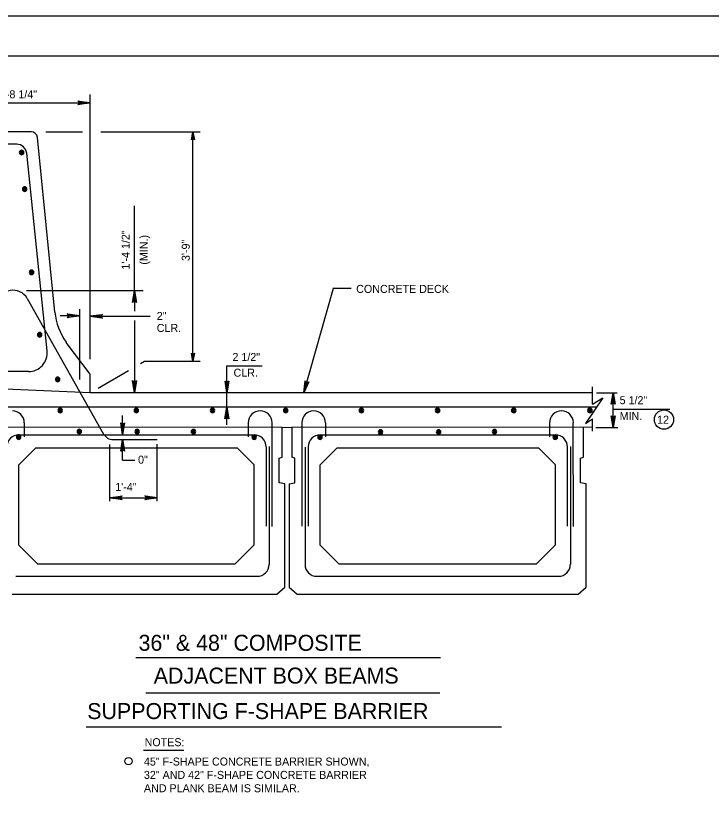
# Model space of a CAD drawing. Extents: x 639331 to 643089, y 299088 to 300975.
# Drawn here: x 641559.1 to 641819.9, y 300574.6 to 300869.7 of the extents above; entities that cross this region are included whole.
import ezdxf

# ---------------------------------------------------------------- set-up
doc = ezdxf.new("R2010")
doc.units = 0
doc.layers.add('1', color=7, linetype='Continuous')
doc.layers.add('PLT-BNDY', color=7, linetype='Continuous')

msp = doc.modelspace()

# ---------------------------------------------------------------- linework, layer by layer
at = {"layer": '1'}
for p, q in [((641433.06, 300854.66), (642219.06, 300854.66)), ((641587.01, 300831.44), (641587.01, 300840.17)), ((641587.01, 300740.96), (641587.01, 300840.17)), ((641540, 300837.03), (641587.01, 300837.03)), ((641564.79, 300826.1), (641541.71, 300826.1)), ((641570.43, 300826.1), (641584.15, 300826.1)), ((641590.95, 300826.1), (641628.21, 300826.1)), ((641625.51, 300740.22), (641625.51, 300826.1)), ((641573.76, 300758.55), (641567.19, 300824.01)), ((641559.45, 300821.54), (641548.32, 300821.54)), ((641561.41, 300818.62), (641561.41, 300818.62)), ((641560.77, 300818.55), (641560.77, 300818.55)), ((641570.86, 300744.07), (641563.19, 300818.15)), ((641561.92, 300804.86), (641561.92, 300804.86)), ((641562.55, 300804.92), (641562.55, 300804.92)), ((641603.65, 300766.76), (641603.65, 300798.41)), ((641564.5, 300773.67), (641564.5, 300773.67)), ((641565.13, 300773.73), (641565.13, 300773.73)), ((641563.09, 300766.76), (641606.91, 300766.76)), ((641603.65, 300766.76), (641603.65, 300758.98)), ((641667.09, 300728.42), (641678.26, 300767.52)), ((641678.01, 300767.52), (641684.88, 300767.52)), ((641563.35, 300763.75), (641592.04, 300712.92)), ((641583.02, 300759.67), (641583.02, 300733.41)), ((641583, 300757.24), (641575.79, 300757.24)), ((641586.99, 300757.03), (641609.51, 300757.03)), ((641603.65, 300755.42), (641603.65, 300728.42)), ((641567.52, 300750.29), (641567.52, 300750.29)), ((641568.15, 300750.35), (641568.15, 300750.35)), ((641587.01, 300735.34), (641578.04, 300747.23)), ((641605.86, 300739.33), (641607.38, 300740.22)), ((641607.38, 300740.22), (641628.21, 300740.22)), ((641563.86, 300736.31), (641554.35, 300736.33)), ((641590, 300730.15), (641601.38, 300736.74)), ((641638.26, 300722.94), (641638.26, 300738.51)), ((641638.26, 300738.51), (641651.49, 300738.51)), ((641574.28, 300733.54), (641574.28, 300733.54)), ((641574.91, 300733.6), (641574.91, 300733.6)), ((641587.01, 300728.42), (641587.01, 300735.34)), ((641587.01, 300728.42), (641542, 300730.28)), ((641775.31, 300724.07), (641775.31, 300730.57)), ((641775.31, 300728.42), (641587.01, 300728.42)), ((641638.26, 300722.94), (641638.26, 300728.42)), ((641776.84, 300728.42), (641784.57, 300728.42)), ((641783.1, 300715.42), (641783.1, 300728.42)), ((641779.23, 300726.46), (641772.75, 300716.91)), ((641775.31, 300724.07), (641779.23, 300726.46)), ((641776.77, 300722.94), (641545.67, 300722.94)), ((641575.22, 300721.92), (641575.22, 300721.92)), ((641575.85, 300721.98), (641575.85, 300721.98)), ((641775.31, 300722.94), (641587.01, 300722.94)), ((641603.78, 300721.92), (641603.78, 300721.92)), ((641604.41, 300721.98), (641604.41, 300721.98)), ((641632.77, 300721.98), (641632.77, 300721.98)), ((641633.4, 300721.92), (641633.4, 300721.92)), ((641638.26, 300716.35), (641638.26, 300722.94)), ((641659.77, 300721.92), (641659.77, 300721.92)), ((641660.4, 300721.98), (641660.4, 300721.98)), ((641688.19, 300721.92), (641688.19, 300721.92)), ((641688.83, 300721.98), (641688.83, 300721.98)), ((641716.75, 300721.92), (641716.75, 300721.92)), ((641717.39, 300721.98), (641717.39, 300721.98)), ((641745.74, 300721.98), (641745.74, 300721.98)), ((641746.37, 300721.92), (641746.37, 300721.92)), ((641774.3, 300721.98), (641774.3, 300721.98)), ((641774.93, 300721.92), (641774.93, 300721.92)), ((641783.1, 300722.29), (641804.35, 300722.29)), ((641599.18, 300712.62), (641599.18, 300719.83)), ((641772.75, 300716.91), (641775.31, 300718.62)), ((641775.31, 300713.94), (641775.31, 300718.62)), ((641659, 300715.42), (641548.62, 300715.54)), ((641562.28, 300717.14), (641562.28, 300711.82)), ((641646.29, 300717.16), (641646.29, 300711.85)), ((641655.25, 300678.3), (641655.2, 300717.16)), ((641659, 300715.42), (641662.59, 300715.54)), ((641659, 300704.3), (641659, 300715.42)), ((641775.31, 300715.42), (641662.59, 300715.54)), ((641662.59, 300715.54), (641662.59, 300704.3)), ((641666.34, 300717.14), (641666.34, 300678.42)), ((641675.25, 300717.14), (641675.25, 300711.82)), ((641759.26, 300717.16), (641759.26, 300711.85)), ((641768.22, 300678.3), (641768.17, 300717.16)), ((641771.97, 300704.3), (641771.97, 300715.42)), ((641776.6, 300715.42), (641784.8, 300715.42)), ((641560.25, 300712.62), (641648.5, 300712.62)), ((641582.41, 300714.01), (641582.41, 300714.01)), ((641604.09, 300714), (641604.09, 300714)), ((641604.73, 300714.06), (641604.73, 300714.06)), ((641625.18, 300713.96), (641625.18, 300713.96)), ((641673.22, 300712.62), (641761.47, 300712.62)), ((641695.34, 300713.8), (641695.34, 300713.8)), ((641717.13, 300713.85), (641717.13, 300713.85)), ((641717.76, 300713.91), (641717.76, 300713.91)), ((641738.1, 300713.96), (641738.1, 300713.96)), ((641559.66, 300711.92), (641559.66, 300711.92)), ((641560.29, 300711.99), (641560.29, 300711.99)), ((641595.58, 300710.83), (641612.08, 300710.83)), ((641599.18, 300703.16), (641599.18, 300710.83)), ((641647.95, 300711.91), (641647.95, 300711.91)), ((641648.59, 300711.97), (641648.59, 300711.97)), ((641673.34, 300712.08), (641673.34, 300712.08)), ((641760.85, 300711.91), (641760.85, 300711.91)), ((641761.83, 300711.73), (641761.83, 300711.73)), ((641560.25, 300701.42), (641566.62, 300707.8)), ((641566.62, 300707.8), (641642.12, 300707.8)), ((641594.38, 300687.75), (641594.38, 300709.02)), ((641612.07, 300687.75), (641612.07, 300709.16)), ((641642.12, 300707.8), (641648.5, 300701.42)), ((641652.95, 300708.16), (641652.95, 300678.42)), ((641654.12, 300708.3), (641654.12, 300664.05)), ((641667.59, 300708.05), (641667.59, 300664.05)), ((641668.76, 300708.16), (641668.76, 300678.42)), ((641673.22, 300701.42), (641679.6, 300707.8)), ((641679.6, 300707.8), (641755.09, 300707.8)), ((641755.09, 300707.8), (641761.47, 300701.42)), ((641765.92, 300708.16), (641765.92, 300678.42)), ((641767.09, 300708.3), (641767.09, 300664.05)), ((641657.87, 300703.92), (641659, 300704.3)), ((641657.87, 300694.67), (641657.87, 300703.92)), ((641663.72, 300703.92), (641662.59, 300704.3)), ((641663.72, 300694.67), (641663.72, 300703.92)), ((641770.84, 300703.92), (641771.97, 300704.3)), ((641770.84, 300694.67), (641770.84, 300703.92)), ((641560.25, 300671.3), (641560.25, 300701.42)), ((641599.18, 300703.16), (641603.76, 300703.16)), ((641648.5, 300671.42), (641648.5, 300701.42)), ((641673.22, 300671.3), (641673.22, 300701.42)), ((641761.47, 300671.42), (641761.47, 300701.42)), ((641660, 300694.3), (641657.87, 300694.67)), ((641661.59, 300694.3), (641663.72, 300694.67)), ((641772.97, 300694.3), (641770.84, 300694.67)), ((641660, 300655.55), (641660, 300694.3)), ((641661.59, 300694.3), (641661.59, 300655.55)), ((641772.97, 300655.55), (641772.97, 300694.3)), ((641594.38, 300689.03), (641612.07, 300689.03)), ((641560.25, 300671.3), (641567.25, 300664.3)), ((641641.37, 300664.3), (641648.5, 300671.42)), ((641673.22, 300671.3), (641680.22, 300664.3)), ((641754.34, 300664.3), (641761.47, 300671.42)), ((641567.25, 300664.3), (641641.37, 300664.3)), ((641680.22, 300664.3), (641754.34, 300664.3)), ((641559.12, 300659.67), (641649.62, 300659.67)), ((641672.09, 300659.67), (641762.59, 300659.67)), ((641657, 300652.92), (641660, 300655.55)), ((641661.59, 300655.55), (641664.59, 300652.92)), ((641769.97, 300652.92), (641772.97, 300655.55)), ((641557.75, 300652.92), (641657, 300652.92)), ((641664.59, 300652.92), (641769.97, 300652.92)), ((641718.36, 300629.07), (641604.1, 300629.07)), ((641718.07, 300615.82), (641607.82, 300615.82)), ((641741.2, 300603.07), (641585.49, 300603.07)), ((641606.94, 300594.49), (641622.1, 300594.49))]:
    msp.add_line(p, q, dxfattribs=at)
for points in [[(641582.65, 300837.57), (641582.81, 300837.26), (641587.01, 300837.03), (641582.65, 300837.57), (641582.43, 300837.77), (641587.01, 300837.03), (641582.82, 300836.82), (641582.66, 300836.51), (641587.01, 300837.03), (641582.43, 300836.3), (641582.66, 300836.51)], [(641625.51, 300826.1), (641626.07, 300823.12), (641625.99, 300823.23), (641625.91, 300823.35), (641625.81, 300823.41), (641625.71, 300823.47), (641625.61, 300823.48), (641625.51, 300823.5), (641625.41, 300823.48), (641625.31, 300823.47), (641625.21, 300823.41), (641625.11, 300823.35), (641625.03, 300823.23), (641624.95, 300823.12), (641625.51, 300826.1), (641625.03, 300823.23), (641625.11, 300823.35), (641625.51, 300826.1), (641625.21, 300823.41), (641625.31, 300823.47), (641625.51, 300826.1), (641625.41, 300823.48), (641625.51, 300823.5), (641625.51, 300826.1), (641625.61, 300823.48), (641625.71, 300823.47), (641625.51, 300826.1), (641625.81, 300823.41), (641625.91, 300823.35), (641625.51, 300826.1), (641625.99, 300823.23)], [(641603.1, 300762.4), (641603.42, 300762.57), (641603.65, 300766.76), (641603.1, 300762.4), (641602.91, 300762.18), (641603.65, 300766.76), (641603.86, 300762.57), (641604.17, 300762.42), (641603.65, 300766.76), (641604.38, 300762.18), (641604.17, 300762.42)], [(641578.64, 300757.79), (641578.81, 300757.48), (641583, 300757.24), (641578.64, 300757.79), (641578.42, 300757.98), (641583, 300757.24), (641578.81, 300757.04), (641578.66, 300756.72), (641583, 300757.24), (641578.42, 300756.52), (641578.66, 300756.72)], [(641591.35, 300756.48), (641591.19, 300756.8), (641586.99, 300757.03), (641591.35, 300756.48), (641591.58, 300756.29), (641586.99, 300757.03), (641591.19, 300757.24), (641591.34, 300757.55), (641586.99, 300757.03), (641591.58, 300757.76), (641591.34, 300757.55)], [(641625.51, 300740.22), (641624.95, 300743.2), (641625.03, 300743.09), (641625.11, 300742.97), (641625.21, 300742.91), (641625.31, 300742.85), (641625.41, 300742.83), (641625.51, 300742.82), (641625.61, 300742.83), (641625.71, 300742.85), (641625.81, 300742.91), (641625.91, 300742.97), (641625.99, 300743.09), (641626.07, 300743.2), (641625.51, 300740.22), (641625.99, 300743.09), (641625.91, 300742.97), (641625.51, 300740.22), (641625.81, 300742.91), (641625.71, 300742.85), (641625.51, 300740.22), (641625.61, 300742.83), (641625.51, 300742.82), (641625.51, 300740.22), (641625.41, 300742.83), (641625.31, 300742.85), (641625.51, 300740.22), (641625.21, 300742.91), (641625.11, 300742.97), (641625.51, 300740.22), (641625.03, 300743.09)], [(641604.2, 300732.78), (641603.88, 300732.62), (641603.65, 300728.42), (641604.2, 300732.78), (641604.39, 300733), (641603.65, 300728.42), (641603.44, 300732.61), (641603.13, 300732.77), (641603.65, 300728.42), (641602.92, 300733), (641603.13, 300732.77)], [(641638.78, 300732.57), (641638.48, 300732.42), (641638.26, 300728.42), (641638.78, 300732.57), (641638.96, 300732.79), (641638.26, 300728.42), (641638.06, 300732.41), (641637.76, 300732.56), (641638.26, 300728.42), (641637.56, 300732.79), (641637.76, 300732.56)], [(641668.72, 300732.28), (641668.39, 300732.21), (641667.09, 300728.42), (641668.72, 300732.28), (641668.95, 300732.43), (641667.09, 300728.42), (641667.98, 300732.32), (641667.74, 300732.54), (641667.09, 300728.42), (641667.61, 300732.81), (641667.74, 300732.54)], [(641782.58, 300724.27), (641782.88, 300724.42), (641783.1, 300728.42), (641782.58, 300724.27), (641782.4, 300724.06), (641783.1, 300728.42), (641783.3, 300724.43), (641783.6, 300724.28), (641783.1, 300728.42), (641783.8, 300724.06), (641783.6, 300724.28)], [(641637.73, 300718.79), (641638.04, 300718.95), (641638.26, 300722.94), (641637.73, 300718.79), (641637.55, 300718.58), (641638.26, 300722.94), (641638.45, 300718.95), (641638.75, 300718.8), (641638.26, 300722.94), (641638.95, 300718.58), (641638.75, 300718.8)], [(641783.62, 300719.57), (641783.32, 300719.42), (641783.1, 300715.42), (641783.62, 300719.57), (641783.81, 300719.79), (641783.1, 300715.42), (641782.91, 300719.41), (641782.61, 300719.56), (641783.1, 300715.42), (641782.41, 300719.79), (641782.61, 300719.56)], [(641599.7, 300716.88), (641599.4, 300716.73), (641599.18, 300712.73), (641599.7, 300716.88), (641599.88, 300717.1), (641599.18, 300712.73), (641598.98, 300716.73), (641598.68, 300716.87), (641599.18, 300712.73), (641598.48, 300717.1), (641598.68, 300716.87)], [(641598.65, 300706.68), (641598.95, 300706.84), (641599.18, 300710.83), (641598.65, 300706.68), (641598.47, 300706.47), (641599.18, 300710.83), (641599.37, 300706.84), (641599.67, 300706.69), (641599.18, 300710.83), (641599.87, 300706.47), (641599.67, 300706.69)], [(641598.74, 300688.48), (641598.58, 300688.8), (641594.38, 300689.03), (641598.74, 300688.48), (641598.96, 300688.29), (641594.38, 300689.03), (641598.57, 300689.24), (641598.73, 300689.55), (641594.38, 300689.03), (641598.96, 300689.76), (641598.73, 300689.55)], [(641607.71, 300689.58), (641607.88, 300689.26), (641612.07, 300689.03), (641607.71, 300689.58), (641607.49, 300689.77), (641612.07, 300689.03), (641607.88, 300688.82), (641607.73, 300688.51), (641612.07, 300689.03), (641607.49, 300688.3), (641607.73, 300688.51)]]:
    msp.add_lwpolyline(points, dxfattribs=at)
for centre, radius in [((641802.15, 300718.33), 3.6), ((641601.39, 300590.32), 1.39)]:
    msp.add_circle(centre, radius, dxfattribs=at)
for centre, radius, start, end in [((641564.82, 300823.76), 2.39, 6.0088, 89.9998), ((641559.45, 300817.78), 3.76, 5.7335, 90), ((641561.3, 300818.4), 0.861, 0, 180), ((641561.3, 300818.4), 0.614, 0, 180), ((641561.3, 300818.4), 0.336, 0, 180), ((641561.3, 300818.4), 0.861, 180, 0), ((641561.3, 300818.4), 0.614, 180, 0), ((641561.3, 300818.4), 0.336, 180, 0), ((641561.3, 300818.4), 0.17, 0, 180), ((641561.3, 300818.4), 0.17, 180, 0), ((641561.3, 300818.4), 0.0726, 0, 180), ((641561.3, 300818.4), 0.0726, 180, 0), ((641562.45, 300804.71), 0.861, 0, 180), ((641562.45, 300804.71), 0.861, 180, 0), ((641562.45, 300804.71), 0.614, 0, 180), ((641562.45, 300804.71), 0.614, 180, 0), ((641562.45, 300804.71), 0.336, 0, 180), ((641562.45, 300804.71), 0.336, 180, 0), ((641562.45, 300804.71), 0.17, 0, 180), ((641562.45, 300804.71), 0.17, 180, 0), ((641562.45, 300804.71), 0.0726, 0, 180), ((641562.45, 300804.71), 0.0726, 180, 0), ((641565.03, 300773.52), 0.861, 0, 180), ((641565.03, 300773.52), 0.861, 180, 0), ((641565.03, 300773.52), 0.614, 0, 180), ((641565.03, 300773.52), 0.614, 180, 0), ((641565.03, 300773.52), 0.336, 0, 180), ((641565.03, 300773.52), 0.336, 180, 0), ((641565.03, 300773.52), 0.17, 0, 180), ((641565.03, 300773.52), 0.17, 180, 0), ((641565.03, 300773.52), 0.0726, 0, 180), ((641565.03, 300773.52), 0.0726, 180, 0), ((641558.14, 300760.79), 5.99, 29.6409, 171.8645), ((641597.5, 300761.05), 23.87, 186.0098, 214.992), ((641568.05, 300750.13), 0.861, 0, 180), ((641568.05, 300750.13), 0.614, 0, 180), ((641568.05, 300750.13), 0.861, 180, 0), ((641568.05, 300750.13), 0.614, 180, 0), ((641568.05, 300750.13), 0.336, 0, 180), ((641568.05, 300750.13), 0.336, 180, 0), ((641568.05, 300750.13), 0.17, 0, 180), ((641568.05, 300750.13), 0.17, 180, 0), ((641568.05, 300750.13), 0.0726, 0, 180), ((641568.05, 300750.13), 0.0726, 180, 0), ((641563.86, 300743.35), 7.04, 270, 5.8377), ((641574.81, 300733.38), 0.861, 0, 180), ((641574.81, 300733.38), 0.861, 180, 0), ((641574.81, 300733.38), 0.614, 0, 180), ((641574.81, 300733.38), 0.614, 180, 0), ((641574.81, 300733.38), 0.336, 0, 180), ((641574.81, 300733.38), 0.336, 180, 0), ((641574.81, 300733.38), 0.17, 0, 180), ((641574.81, 300733.38), 0.17, 180, 0), ((641574.81, 300733.38), 0.0726, 0, 180), ((641574.81, 300733.38), 0.0726, 180, 0), ((641557.83, 300717.14), 4.46, 359.9997, 90), ((641575.75, 300721.76), 0.861, 0, 180), ((641575.75, 300721.76), 0.861, 180, 0), ((641575.75, 300721.76), 0.614, 0, 180), ((641575.75, 300721.76), 0.614, 180, 0), ((641575.75, 300721.76), 0.336, 0, 180), ((641575.75, 300721.76), 0.336, 180, 0), ((641575.75, 300721.76), 0.17, 0, 180), ((641575.75, 300721.76), 0.17, 180, 0), ((641575.75, 300721.76), 0.0726, 0, 180), ((641575.75, 300721.76), 0.0726, 180, 0), ((641604.31, 300721.76), 0.861, 0, 180), ((641604.31, 300721.76), 0.861, 180, 0), ((641604.31, 300721.76), 0.614, 0, 180), ((641604.31, 300721.76), 0.614, 180, 0), ((641604.31, 300721.76), 0.336, 0, 180), ((641604.31, 300721.76), 0.336, 180, 0), ((641604.31, 300721.76), 0.17, 0, 180), ((641604.31, 300721.76), 0.17, 180, 0), ((641604.31, 300721.76), 0.0726, 0, 180), ((641604.31, 300721.76), 0.0726, 180, 0), ((641632.87, 300721.76), 0.861, 0, 180), ((641632.87, 300721.76), 0.861, 180, 0), ((641632.87, 300721.76), 0.614, 0, 180), ((641632.87, 300721.76), 0.614, 180, 0), ((641632.87, 300721.76), 0.336, 0, 180), ((641632.87, 300721.76), 0.336, 180, 0), ((641632.87, 300721.76), 0.17, 0, 180), ((641632.87, 300721.76), 0.17, 180, 0), ((641632.87, 300721.76), 0.0726, 0, 180), ((641632.87, 300721.76), 0.0726, 180, 0), ((641650.74, 300717.16), 4.46, 90, 180.0003), ((641650.74, 300717.16), 4.46, 0, 90), ((641660.3, 300721.76), 0.861, 0, 180), ((641660.3, 300721.76), 0.861, 180, 0), ((641660.3, 300721.76), 0.614, 0, 180), ((641660.3, 300721.76), 0.614, 180, 0), ((641660.3, 300721.76), 0.336, 0, 180), ((641660.3, 300721.76), 0.336, 180, 0), ((641660.3, 300721.76), 0.17, 0, 180), ((641660.3, 300721.76), 0.17, 180, 0), ((641660.3, 300721.76), 0.0726, 0, 180), ((641660.3, 300721.76), 0.0726, 180, 0), ((641670.8, 300717.14), 4.46, 90, 180), ((641670.8, 300717.14), 4.46, 0, 90), ((641688.72, 300721.76), 0.861, 0, 180), ((641688.72, 300721.76), 0.861, 180, 0), ((641688.72, 300721.76), 0.614, 0, 180), ((641688.72, 300721.76), 0.614, 180, 0), ((641688.72, 300721.76), 0.336, 0, 180), ((641688.72, 300721.76), 0.336, 180, 0), ((641688.72, 300721.76), 0.17, 0, 180), ((641688.72, 300721.76), 0.17, 180, 0), ((641688.72, 300721.76), 0.0726, 0, 180), ((641688.72, 300721.76), 0.0726, 180, 0), ((641717.28, 300721.76), 0.861, 0, 180), ((641717.28, 300721.76), 0.861, 180, 0), ((641717.28, 300721.76), 0.614, 0, 180), ((641717.28, 300721.76), 0.614, 180, 0), ((641717.28, 300721.76), 0.336, 0, 180), ((641717.28, 300721.76), 0.336, 180, 0), ((641717.28, 300721.76), 0.17, 0, 180), ((641717.28, 300721.76), 0.17, 180, 0), ((641717.28, 300721.76), 0.0726, 0, 180), ((641717.28, 300721.76), 0.0726, 180, 0), ((641745.84, 300721.76), 0.861, 0, 180), ((641745.84, 300721.76), 0.861, 180, 0), ((641745.84, 300721.76), 0.614, 0, 180), ((641745.84, 300721.76), 0.614, 180, 0), ((641745.84, 300721.76), 0.336, 0, 180), ((641745.84, 300721.76), 0.336, 180, 0), ((641745.84, 300721.76), 0.17, 0, 180), ((641745.84, 300721.76), 0.17, 180, 0), ((641745.84, 300721.76), 0.0726, 0, 180), ((641745.84, 300721.76), 0.0726, 180, 0), ((641763.72, 300717.16), 4.46, 90, 180.0003), ((641763.72, 300717.16), 4.46, 0, 90), ((641774.4, 300721.76), 0.861, 0, 180), ((641774.4, 300721.76), 0.861, 180, 0), ((641774.4, 300721.76), 0.614, 0, 180), ((641774.4, 300721.76), 0.614, 180, 0), ((641774.4, 300721.76), 0.336, 0, 180), ((641774.4, 300721.76), 0.336, 180, 0), ((641774.4, 300721.76), 0.17, 0, 180), ((641774.4, 300721.76), 0.17, 180, 0), ((641774.4, 300721.76), 0.0726, 0, 180), ((641774.4, 300721.76), 0.0726, 180, 0), ((641560.25, 300708.16), 4.46, 90, 180.0003), ((641560.19, 300711.77), 0.861, 0, 180), ((641560.19, 300711.77), 0.614, 0, 180), ((641582.94, 300713.86), 0.861, 0, 180), ((641582.94, 300713.86), 0.861, 180, 0), ((641582.94, 300713.86), 0.614, 0, 180), ((641582.94, 300713.86), 0.614, 180, 0), ((641582.94, 300713.86), 0.336, 0, 180), ((641582.94, 300713.86), 0.336, 180, 0), ((641582.94, 300713.86), 0.17, 0, 180), ((641582.94, 300713.86), 0.17, 180, 0), ((641582.94, 300713.86), 0.0726, 0, 180), ((641582.94, 300713.86), 0.0726, 180, 0), ((641595.61, 300714.98), 4.12, 209.9181, 270), ((641604.62, 300713.84), 0.861, 0, 180), ((641604.62, 300713.84), 0.861, 180, 0), ((641604.62, 300713.84), 0.614, 0, 180), ((641604.62, 300713.84), 0.614, 180, 0), ((641604.62, 300713.84), 0.336, 0, 180), ((641604.62, 300713.84), 0.336, 180, 0), ((641604.62, 300713.84), 0.17, 0, 180), ((641604.62, 300713.84), 0.17, 180, 0), ((641604.62, 300713.84), 0.0726, 0, 180), ((641604.62, 300713.84), 0.0726, 180, 0), ((641625.71, 300713.81), 0.861, 0, 180), ((641625.71, 300713.81), 0.861, 180, 0), ((641625.71, 300713.81), 0.614, 0, 180), ((641625.71, 300713.81), 0.614, 180, 0), ((641625.71, 300713.81), 0.336, 0, 180), ((641625.71, 300713.81), 0.336, 180, 0), ((641625.71, 300713.81), 0.17, 0, 180), ((641625.71, 300713.81), 0.17, 180, 0), ((641625.71, 300713.81), 0.0726, 0, 180), ((641625.71, 300713.81), 0.0726, 180, 0), ((641648.48, 300711.75), 0.861, 0, 180), ((641648.48, 300711.75), 0.614, 0, 180), ((641648.5, 300708.16), 4.46, 359.9997, 90), ((641673.22, 300708.16), 4.46, 90, 180), ((641673.19, 300711.76), 0.861, 0, 180), ((641673.19, 300711.76), 0.614, 0, 180), ((641695.87, 300713.65), 0.861, 0, 180), ((641695.87, 300713.65), 0.861, 180, 0), ((641695.87, 300713.65), 0.614, 0, 180), ((641695.87, 300713.65), 0.614, 180, 0), ((641695.87, 300713.65), 0.336, 0, 180), ((641695.87, 300713.65), 0.336, 180, 0), ((641695.87, 300713.65), 0.17, 0, 180), ((641695.87, 300713.65), 0.17, 180, 0), ((641695.87, 300713.65), 0.0726, 0, 180), ((641695.87, 300713.65), 0.0726, 180, 0), ((641717.66, 300713.69), 0.861, 0, 180), ((641717.66, 300713.69), 0.861, 180, 0), ((641717.66, 300713.69), 0.614, 0, 180), ((641717.66, 300713.69), 0.614, 180, 0), ((641717.66, 300713.69), 0.336, 0, 180), ((641717.66, 300713.69), 0.336, 180, 0), ((641717.66, 300713.69), 0.17, 0, 180), ((641717.66, 300713.69), 0.17, 180, 0), ((641717.66, 300713.69), 0.0726, 0, 180), ((641717.66, 300713.69), 0.0726, 180, 0), ((641738.63, 300713.8), 0.861, 0, 180), ((641738.63, 300713.8), 0.861, 180, 0), ((641738.63, 300713.8), 0.614, 0, 180), ((641738.63, 300713.8), 0.614, 180, 0), ((641738.63, 300713.8), 0.336, 0, 180), ((641738.63, 300713.8), 0.336, 180, 0), ((641738.63, 300713.8), 0.17, 0, 180), ((641738.63, 300713.8), 0.17, 180, 0), ((641738.63, 300713.8), 0.0726, 0, 180), ((641738.63, 300713.8), 0.0726, 180, 0), ((641761.38, 300711.76), 0.861, 0, 180), ((641761.38, 300711.76), 0.614, 0, 180), ((641761.47, 300708.16), 4.46, 0, 90), ((641560.19, 300711.77), 0.861, 180, 0), ((641560.19, 300711.77), 0.614, 180, 0), ((641560.19, 300711.77), 0.336, 0, 180), ((641560.19, 300711.77), 0.336, 180, 0), ((641560.19, 300711.77), 0.17, 0, 180), ((641560.19, 300711.77), 0.17, 180, 0), ((641560.19, 300711.77), 0.0726, 0, 180), ((641560.19, 300711.77), 0.0726, 180, 0), ((641648.48, 300711.75), 0.861, 180, 0), ((641648.48, 300711.75), 0.614, 180, 0), ((641648.48, 300711.75), 0.336, 0, 180), ((641648.48, 300711.75), 0.336, 180, 0), ((641648.48, 300711.75), 0.17, 0, 180), ((641648.48, 300711.75), 0.17, 180, 0), ((641648.48, 300711.75), 0.0726, 0, 180), ((641648.48, 300711.75), 0.0726, 180, 0), ((641673.19, 300711.76), 0.861, 180, 0), ((641673.19, 300711.76), 0.614, 180, 0), ((641673.19, 300711.76), 0.336, 0, 180), ((641673.19, 300711.76), 0.336, 180, 0), ((641673.19, 300711.76), 0.17, 0, 180), ((641673.19, 300711.76), 0.17, 180, 0), ((641673.19, 300711.76), 0.0726, 0, 180), ((641673.19, 300711.76), 0.0726, 180, 0), ((641761.38, 300711.76), 0.861, 180, 0), ((641761.38, 300711.76), 0.614, 180, 0), ((641761.38, 300711.76), 0.336, 0, 180), ((641761.38, 300711.76), 0.336, 180, 0), ((641761.38, 300711.76), 0.17, 0, 180), ((641761.38, 300711.76), 0.17, 180, 0), ((641761.38, 300711.76), 0.0726, 0, 180), ((641761.38, 300711.76), 0.0726, 180, 0), ((641649.61, 300664.08), 4.46, 270, 0), ((641672.03, 300664.08), 4.46, 180, 270), ((641762.58, 300664.08), 4.46, 270, 0)]:
    msp.add_arc(centre, radius, start, end, dxfattribs=at)
at = {"layer": 'PLT-BNDY'}
msp.add_lwpolyline([(641393.06, 300869.66), (642234.06, 300869.66), (642234.06, 300275.66), (641393.06, 300275.66)], close=True, dxfattribs=at)

# ---------------------------------------------------------------- texts
at = {"layer": '1'}
for s, height, p in [('1\'-8 1/4"', 3, (641552.4, 300838.72)), ('CONCRETE DECK', 3, (641686.75, 300765.8)), ('2"', 3, (641611.97, 300755.67)), ('CLR.', 3, (641611.97, 300751.17)), ('2 1/2"', 3, (641640.36, 300740.29)), ('CLR.', 3, (641640.77, 300734.4)), ('5 1/2"', 3, (641785.54, 300724.1)), ('MIN.', 3, (641785.54, 300718.17)), ('12', 3, (641799.58, 300716.79)), ('0"', 3, (641604.96, 300701.81)), ('1\'-4"', 3, (641596.41, 300691.58)), ('36" & 48" COMPOSITE', 6, (641605.14, 300631.69)), ('ADJACENT BOX BEAMS', 6, (641610.84, 300619.4)), ('SUPPORTING F-SHAPE BARRIER', 6, (641585.9, 300606.11)), ('NOTES:', 3, (641607.42, 300595.95)), ('45" F-SHAPE CONCRETE BARRIER SHOWN,', 3, (641607.16, 300588.69)), ('32" AND 42" F-SHAPE CONCRETE BARRIER ', 3, (641607.16, 300583.69)), ('AND PLANK BEAM IS SIMILAR.', 3, (641607.16, 300578.69))]:
    msp.add_text(s, height=height, dxfattribs=at).set_placement(p)
for s, p in [('1\'-4 1/2"', (641601.82, 300774.56)), ('(MIN.)', (641608.6, 300776.38)), ('3\'-9"', (641624.34, 300777.74))]:
    msp.add_text(s, height=3, rotation=90, dxfattribs=at).set_placement(p)

doc.saveas('drawing.dxf')
